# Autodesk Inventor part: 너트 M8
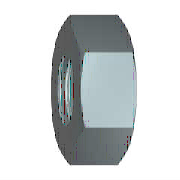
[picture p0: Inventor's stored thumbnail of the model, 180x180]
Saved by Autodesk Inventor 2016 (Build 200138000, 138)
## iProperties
IsCustomPart: 1
Created: 2012-02
Part Number: 너트 M8
Material: 강철, 연강
Description: 6각 너트 및 6각 가는 너트
Document SubType Name: Modeling
Standard: KS B 1012
Designer: mduedu
Standards Organization: KS
Language: ko-KR
Size Designation: M 8
Categories: <MemberInstance><Categories><Category DisplayName="조임쇠" InternalName="e4da775c-781d-43d5-af7c-5136215cf5a6" Mnemonic="FSTN"><Category DisplayName="너트" InternalN
Density: 1 g/cm^3
Appearance: 강철
Author: mduedu
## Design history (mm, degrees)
sketch "스케치1"
  geometry: L1 (-7.506, 0)-(-3.753, 6.5); L2 (-3.753, 6.5)-(3.753, 6.5); L3 (3.753, 6.5)-(7.506, 0); L4 (7.506, 0)-(3.753, -6.5); L5 (3.753, -6.5)-(-3.753, -6.5); L6 (-3.753, -6.5)-(-7.506, 0); 2 further points
  constraints: 12 end point, 1 coincident, 1 horizontal, 11 other
  dimensions: "d0" = 15.01111 distance of L3.end L1.start (= 1.1547 x SW)
extrude "본체" new body sketch "스케치1" distance "d1" = 5 (= KOH); taper "d2" = 0 deg
sketch "스케치2"
  geometry: L1 (0, 3.753)-(0, 7.506) reference; L2 (0, 7.506)-(5, 7.506) reference; L3 (5, 3.753)-(5, 7.506) reference; L4 (-1, 0)-(6, 0) reference; L5 (0.581, 7.506)-(0, 6.5); L6 (4.419, 7.506)-(5, 6.5)
  constraints: 4 end point, 4 point on line
  dimensions: "d3" = 30 deg angle of L1 L5 (= ANG1); "d4" = 30 deg angle of L3 L6 (= ANG2); "d5" = 13 diameter of L5.end L4 (= SW0); "d6" = 13 diameter of L6.end L4 (= SW01)
revolve "모따기1" sketch "스케치2" stored, may be unused: angle "d7" = 90 deg
sketch "스케치3"
  geometry: A1 r 6.5 centre (0, 0) between (-3.25, -5.629) and (3.25, -5.629) reference; 1 further point
  constraints: 1 coincident
hole "스레드" sketch "스케치3" at (0, 0) diameter "d25" = 6.647; stored, may be unused: countersink angle "d29" = 82 deg, drill point angle "d31" = 118 deg; dims "d26" = 6, "d27" = 4, "d28" = 2, "d30" = 8
workaxis "Work Axis1"
workplane "Work Plane1"
body "Solid1"
chamfer "모따기2" distance "d8" = 0.67658 (= -0.5 x GD1 + 0.5 x NND); stored, may be unused: angle "d9" = 30 deg, second distance "d40" = 0.67658 (= -0.5 x GD1 + 0.5 x NND)
chamfer "모따기3" distance "d10" = 0.67658 (= -0.5 x GD1 + 0.5 x NND); stored, may be unused: angle "d11" = 30 deg, second distance "d41" = 0.67658 (= -0.5 x GD1 + 0.5 x NND)
other parameters: "ANG1" = 30 deg [user parameter; used in 1 equation term], "ANG2" = 30 deg [user parameter; used in 1 equation term], "NND" = 8 [user parameter; used in 4 equation terms], "KOH" = 5 [user parameter; used in 1 equation term], "SW" = 13 [user parameter; used in 4 equation terms], "SW0" = 13 (= SW) [user parameter; used in 1 equation term], "SW01" = 13 (= SW) [user parameter; used in 1 equation term], "GD1" = 6.64684 (computed from THREADDIA, PTC, TOA) [user parameter; used in 4 equation terms], "d13" = 0, "d14" = 0, "d39" = 0, "d42" = 0, "GUL" = 0.67658 (= 0.541266 x PTC) [user parameter], "TPU" = 8 (computed from PTC) [user parameter], "THREADDIA" = 8 [user parameter; used in 1 equation term], "TOA" = 30 deg [user parameter; used in 1 equation term], "PTC" = 1.25 [user parameter; used in 4 equation terms], "E0" = 15.015 (= 1.155 x SW) [user parameter], "GAL" = 0.67658 (= 0.541266 x PTC) [user parameter]
